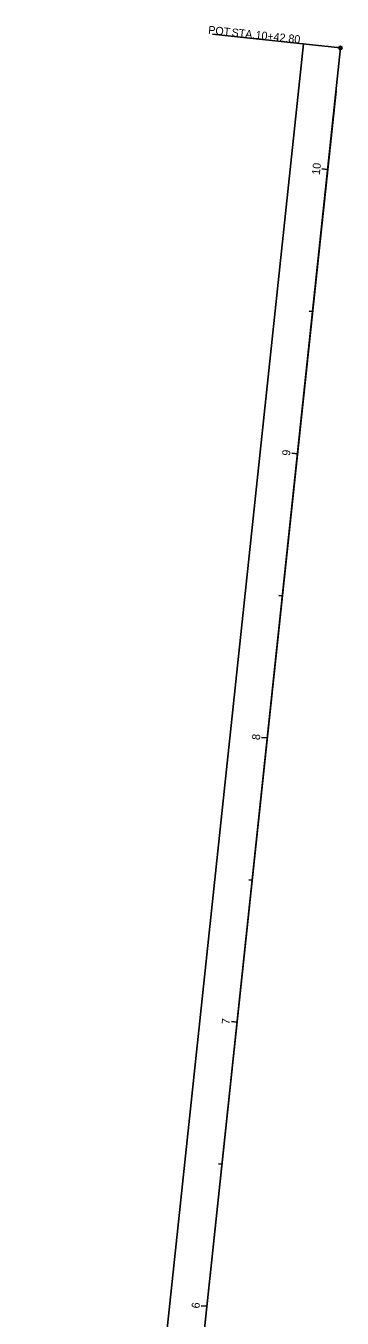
# Model space of a CAD drawing. Extents: x 1369241 to 1370511, y 405374 to 406419.
# Drawn here: x 1369966.4 to 1370077.2, y 405966.8 to 406419 of the extents above; entities that cross this region are included whole.
import ezdxf

# ---------------------------------------------------------------- set-up
doc = ezdxf.new("R2010")
doc.units = 0
for name, color, linetype in [('DT_P_Contour_Major', 7, 'Continuous'), ('GE_P_Alignment_100_Cardinal_Points', 7, 'Continuous'), ('GE_P_Alignment_100_Stations', 7, 'Continuous'), ('RW_X_CL', 7, 'Continuous'), ('SG_P_Poles', 7, 'Continuous')]:
    doc.layers.add(name, color=color, linetype=linetype)

msp = doc.modelspace()

# ---------------------------------------------------------------- linework, layer by layer
at = {"layer": 'DT_P_Contour_Major'}
msp.add_line((1370003.71, 405848.05), (1370063.7, 406412.63), dxfattribs=at)
at = {"layer": 'GE_P_Alignment_100_Cardinal_Points'}
msp.add_line((1370076.62, 406411.25), (1370031.87, 406416.01), dxfattribs=at)
msp.add_circle((1370076.62, 406411.25), 0.6, dxfattribs=at)
at = {"layer": 'GE_P_Alignment_100_Stations'}
for p, q in [((1370072.1, 406368.69), (1370070.11, 406368.9)), ((1370066.82, 406318.97), (1370065.62, 406319.1)), ((1370061.53, 406269.25), (1370059.55, 406269.46)), ((1370056.25, 406219.53), (1370055.06, 406219.66)), ((1370050.97, 406169.81), (1370048.98, 406170.02)), ((1370045.69, 406120.09), (1370044.49, 406120.22)), ((1370040.4, 406070.37), (1370038.42, 406070.58)), ((1370035.12, 406020.65), (1370033.93, 406020.78)), ((1370029.84, 405970.93), (1370027.85, 405971.14))]:
    msp.add_line(p, q, dxfattribs=at)
at = {"layer": 'RW_X_CL'}
msp.add_line((1370023.41, 405910.39), (1370075.13, 406396.09), dxfattribs=at)
at = {"layer": 'SG_P_Poles'}
msp.add_line((1369966.45, 405374.29), (1370076.62, 406411.25), dxfattribs=at)

# ---------------------------------------------------------------- texts
at = {"layer": 'GE_P_Alignment_100_Cardinal_Points'}
for s, p in [('POT', (1370030.21, 406416.23)), (' STA. ', (1370037.37, 406415.47)), ('10+42.80', (1370046.77, 406414.47))]:
    msp.add_text(s, height=2.8, rotation=353.9352, dxfattribs=at).set_placement(p)
at = {"layer": 'GE_P_Alignment_100_Stations'}
for s, p in [('10', (1370069.38, 406366.74)), ('9', (1370058.93, 406268.44)), ('8', (1370048.37, 406168.98)), ('7', (1370037.79, 406069.46)), ('6', (1370027.23, 405970.08))]:
    msp.add_text(s, height=2.8, rotation=83.9352, dxfattribs=at).set_placement(p)

doc.saveas('drawing.dxf')
